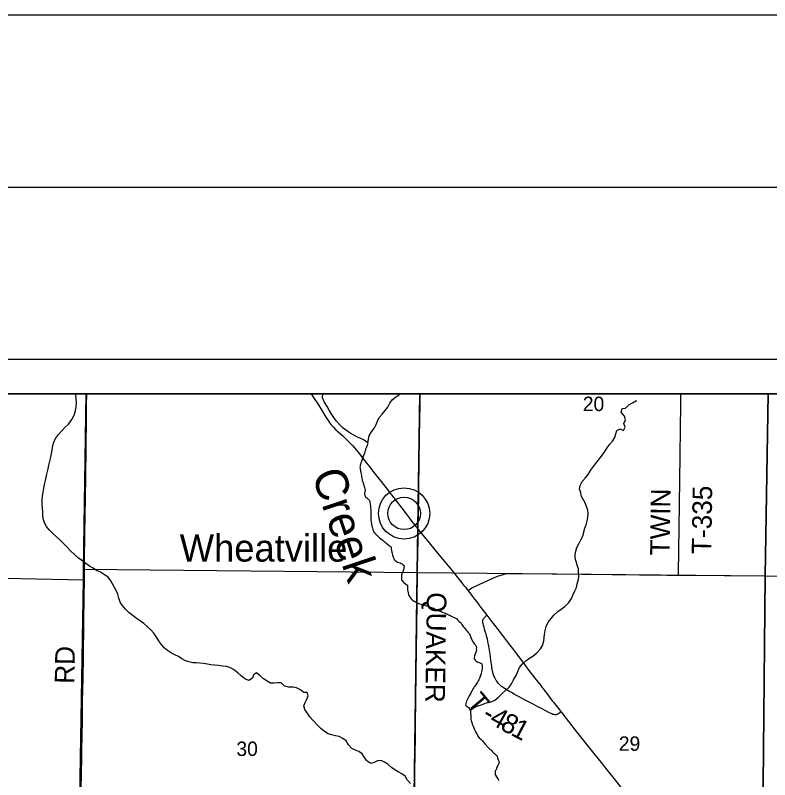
# Model space of a CAD drawing. Extents: x 0 to 34, y 0 to 22.
# Drawn here: x 3.317 to 5.509, y 19.778 to 22 of the extents above; entities that cross this region are included whole.
import ezdxf

# ---------------------------------------------------------------- set-up
doc = ezdxf.new("R2010")
doc.units = 0
for name, color, linetype in [('GM_X_Corporation', 7, 'Continuous'), ('GM_X_County_Road', 7, 'Continuous'), ('GM_X_County_Road_Text', 7, 'Continuous'), ('GM_X_Minor_River', 7, 'Continuous'), ('GM_X_Minor_River_Text', 7, 'Continuous'), ('GM_X_Section_Text', 7, 'Continuous'), ('GM_X_State_Route', 7, 'Continuous'), ('GM_X_Township_Road', 7, 'Continuous'), ('GM_X_Township_Road_Text', 7, 'Continuous'), ('GM_X_Unincorporated', 7, 'Continuous'), ('GM_X_Unincorporated_Location', 7, 'Continuous'), ('GM_X_Unincorporated_Text', 7, 'Continuous'), ('SH_Border', 7, 'Continuous'), ('SH_Cut_Line', 7, 'Continuous'), ('SH_Data', 7, 'Continuous')]:
    doc.layers.add(name, color=color, linetype=linetype)

msp = doc.modelspace()

# ---------------------------------------------------------------- linework, layer by layer
at = {"layer": 'GM_X_Corporation'}
for points in [[(3.5082, 19.7748), (3.5095, 19.8637), (3.511, 19.9493), (3.5112, 20.0053), (3.5125, 20.0737), (3.5137, 20.1344), (3.5145, 20.2333), (3.5155, 20.3135), (3.5163, 20.3526), (3.5169, 20.4148), (3.5181, 20.4924), (3.5191, 20.549), (3.5197, 20.5949), (3.5203, 20.6635), (3.5214, 20.7384), (3.5224, 20.8347), (3.5228, 20.8664), (3.5231, 20.9), (2.1, 20.9)], [(8.9, 20.9), (3.5231, 20.9), (3.5228, 20.8664), (3.5224, 20.8347), (3.5214, 20.7384), (3.5203, 20.6635), (3.5197, 20.5949), (3.5191, 20.549), (3.5181, 20.4924), (3.5169, 20.4148), (3.5163, 20.3526), (3.5155, 20.3135), (3.5145, 20.2333), (3.5137, 20.1344), (3.5125, 20.0737), (3.5112, 20.0053), (3.511, 19.9493), (3.5095, 19.8637), (3.5082, 19.7748)]]:
    msp.add_lwpolyline(points, dxfattribs=at)
for points in [[(3.5223, 20.9), (2.5175, 20.9), (2.5086, 20.3801), (3.5147, 20.359), (3.5146, 20.3904)], [(4.4918, 20.9), (3.5223, 20.9), (3.5146, 20.3904), (4.4842, 20.3804)], [(5.5043, 20.9), (4.4918, 20.9), (4.4842, 20.3804), (5.4958, 20.3705)], [(6.4979, 20.9), (5.5043, 20.9), (5.4958, 20.3705), (6.4927, 20.3511)], [(2.5086, 20.3801), (3.5147, 20.359), (3.4987, 19.3808), (2.4933, 19.3936)], [(3.5146, 20.3904), (4.4842, 20.3804), (4.4706, 19.3704), (3.4987, 19.3808), (3.5147, 20.359)], [(4.4842, 20.3804), (5.4958, 20.3705), (5.4859, 19.36), (4.4706, 19.3704)], [(5.4958, 20.3705), (6.4927, 20.3511), (6.4855, 19.3379), (5.4859, 19.36)]]:
    msp.add_lwpolyline(points, close=True, dxfattribs=at)
at = {"layer": 'GM_X_County_Road'}
msp.add_lwpolyline([(4.4772, 19.7476), (4.4779, 19.8035), (4.4785, 19.8518), (4.4793, 19.9021), (4.4797, 19.9332), (4.4798, 19.9611), (4.4802, 19.986), (4.4807, 20.0239), (4.4815, 20.076), (4.4818, 20.1021), (4.4823, 20.1394), (4.4826, 20.1698), (4.4832, 20.2058), (4.4836, 20.2444), (4.4839, 20.2711), (4.4845, 20.3077), (4.4846, 20.3257), (4.485, 20.3492), (4.4853, 20.3722), (4.4858, 20.4057), (4.4863, 20.4374), (4.4869, 20.4716), (4.4874, 20.5057), (4.4888, 20.6048), (4.4905, 20.7229), (4.4914, 20.7775), (4.492, 20.8205), (4.4929, 20.8733), (4.4933, 20.9)], dxfattribs=at)
at = {"layer": 'GM_X_Minor_River'}
for points in [[(3.8209, 20.1204), (3.8111, 20.1236), (3.8002, 20.1295), (3.7904, 20.1358), (3.7803, 20.1413), (3.7702, 20.1464), (3.7589, 20.1538), (3.7488, 20.1612), (3.7407, 20.172), (3.734, 20.182), (3.727, 20.1928), (3.7192, 20.2043), (3.7103, 20.214), (3.7006, 20.2225), (3.6902, 20.2322), (3.6804, 20.2392), (3.6688, 20.247), (3.6587, 20.2544), (3.6479, 20.2634), (3.637, 20.2734), (3.6274, 20.285), (3.6211, 20.2946), (3.6175, 20.3057), (3.6143, 20.3175), (3.6096, 20.3279), (3.5993, 20.347), (3.5938, 20.3566), (3.5868, 20.367), (3.5755, 20.3737), (3.5639, 20.3811), (3.553, 20.3863), (3.5429, 20.3925), (3.532, 20.3988), (3.5215, 20.4062), (3.5103, 20.4152), (3.5005, 20.4225), (3.4904, 20.4303), (3.4755, 20.445), (3.4666, 20.4547), (3.4569, 20.4648), (3.4469, 20.4748), (3.4353, 20.4853), (3.4256, 20.4942), (3.4155, 20.5043), (3.407, 20.5139), (3.4011, 20.5243), (3.3983, 20.5338), (3.3962, 20.5445), (3.3964, 20.5563), (3.3955, 20.5673), (3.3949, 20.5798), (3.3951, 20.5905), (3.3957, 20.603), (3.3975, 20.614), (3.3996, 20.6257), (3.4017, 20.6359), (3.4045, 20.6477), (3.4075, 20.662), (3.4124, 20.6817), (3.4145, 20.6919), (3.4202, 20.7157), (3.4219, 20.726), (3.4236, 20.7358), (3.4258, 20.7491), (3.429, 20.7596), (3.4333, 20.7694), (3.4423, 20.7818), (3.4523, 20.7919), (3.4609, 20.8016), (3.4709, 20.812), (3.4807, 20.8255), (3.4877, 20.8379), (3.4917, 20.85), (3.4939, 20.8629), (3.4941, 20.8735), (3.4932, 20.8857), (3.4926, 20.8967), (3.4923, 20.9)], [(4.3406, 20.7571), (4.3306, 20.7649), (4.3204, 20.7696), (4.3107, 20.774), (4.3005, 20.7795), (4.29, 20.7858), (4.2795, 20.7928), (4.269, 20.8002), (4.2586, 20.811), (4.2504, 20.8207), (4.2423, 20.8311), (4.2349, 20.8422), (4.229, 20.8518), (4.2228, 20.863), (4.2143, 20.876), (4.2096, 20.8883), (4.2105, 20.8993), (4.2106, 20.9)], [(4.3406, 20.7571), (4.3445, 20.7775), (4.3512, 20.7888), (4.3605, 20.8008), (4.3656, 20.8109), (4.3692, 20.8207), (4.3739, 20.8305), (4.3825, 20.8402), (4.3914, 20.8511), (4.3988, 20.8612), (4.4047, 20.8721), (4.4121, 20.8818), (4.4221, 20.8911), (4.4317, 20.897), (4.4343, 20.9)], [(4.6381, 19.9806), (4.6486, 19.9867), (4.6582, 19.9915), (4.6681, 19.9951), (4.6781, 19.9983), (4.6884, 20.0023), (4.6994, 20.004), (4.7105, 20.0091), (4.7205, 20.0177), (4.731, 20.0285), (4.7418, 20.0382), (4.7514, 20.0475), (4.7588, 20.0572), (4.7647, 20.0685), (4.773, 20.0831), (4.7769, 20.0929), (4.7821, 20.1038), (4.7899, 20.1143), (4.7999, 20.124), (4.8107, 20.131), (4.8206, 20.1373), (4.8318, 20.1473), (4.8423, 20.1582), (4.8482, 20.1683), (4.8522, 20.1811), (4.8535, 20.191), (4.8541, 20.2005), (4.8565, 20.2118), (4.8594, 20.2235), (4.8646, 20.2356), (4.8735, 20.2468), (4.8817, 20.2565), (4.8932, 20.2669), (4.9028, 20.274), (4.9132, 20.2817), (4.9248, 20.2929), (4.9326, 20.3049), (4.9378, 20.3162), (4.9429, 20.3271), (4.9473, 20.3369), (4.9497, 20.3479), (4.953, 20.3596), (4.9539, 20.3698), (4.9534, 20.3808), (4.9528, 20.3911), (4.9496, 20.4018), (4.9467, 20.4121), (4.9439, 20.422), (4.9437, 20.4323), (4.945, 20.4421), (4.9487, 20.4534), (4.9542, 20.4636), (4.9604, 20.4749), (4.9667, 20.4877), (4.9688, 20.4986), (4.9717, 20.5088), (4.9757, 20.5194), (4.9785, 20.5303), (4.9802, 20.5406), (4.9816, 20.5516), (4.9799, 20.5611), (4.9766, 20.5721), (4.9723, 20.5829), (4.9613, 20.6028), (4.9603, 20.6131), (4.9556, 20.623), (4.9577, 20.6336), (4.9639, 20.6445), (4.9725, 20.6546), (4.981, 20.6655), (4.9884, 20.6771), (5.0056, 20.7003), (5.0145, 20.7112), (5.0219, 20.7216), (5.0297, 20.7321), (5.0363, 20.7423), (5.0433, 20.7524), (5.0522, 20.7621), (5.0589, 20.773), (5.0614, 20.7836), (5.0642, 20.7934), (5.0741, 20.7981), (5.0839, 20.793), (5.089, 20.8032), (5.085, 20.8131), (5.0902, 20.8244), (5.0866, 20.8351), (5.0769, 20.8463), (5.0798, 20.8572), (5.0897, 20.8578), (5.0993, 20.8675), (5.1097, 20.8734), (5.1193, 20.8793), (5.1223, 20.8796)], [(4.3406, 20.7571), (4.3388, 20.7492), (4.3372, 20.745), (4.3359, 20.7428), (4.3347, 20.7386), (4.3338, 20.736), (4.3325, 20.7318), (4.3309, 20.7277), (4.3271, 20.7176), (4.3262, 20.7149), (4.3254, 20.7115), (4.3241, 20.7085), (4.3233, 20.7059), (4.3224, 20.7029), (4.3211, 20.6987), (4.3202, 20.6946), (4.319, 20.6916), (4.3185, 20.6889), (4.3181, 20.6866), (4.3183, 20.6836), (4.319, 20.6809), (4.3193, 20.6782), (4.3199, 20.6744), (4.3209, 20.6705), (4.3215, 20.6663), (4.3225, 20.6621), (4.3228, 20.6586), (4.3234, 20.6544), (4.3244, 20.651), (4.325, 20.6475), (4.3264, 20.644), (4.3271, 20.6413), (4.3284, 20.6371), (4.3311, 20.6271), (4.3325, 20.6236), (4.3332, 20.6217), (4.3331, 20.6198), (4.3317, 20.6107), (4.3316, 20.608), (4.3319, 20.6049), (4.3336, 20.6014), (4.3355, 20.5995), (4.338, 20.5975), (4.3402, 20.5955), (4.3432, 20.5927), (4.3457, 20.59), (4.3464, 20.588), (4.347, 20.5834), (4.348, 20.5781), (4.3486, 20.5731), (4.3487, 20.5677), (4.3494, 20.5639), (4.3496, 20.5597), (4.3497, 20.5528), (4.3499, 20.5464), (4.3501, 20.541), (4.35, 20.5376), (4.3502, 20.5338), (4.3501, 20.5311), (4.3504, 20.528), (4.3511, 20.5257), (4.3513, 20.5227), (4.3519, 20.5181), (4.3526, 20.5161), (4.3537, 20.5142), (4.3536, 20.5123), (4.3543, 20.5104), (4.3552, 20.5046), (4.3563, 20.5027), (4.3574, 20.5003), (4.3588, 20.498), (4.361, 20.4956), (4.3628, 20.4933), (4.3654, 20.4909), (4.368, 20.4893), (4.3687, 20.4874), (4.3712, 20.485), (4.3749, 20.4814), (4.3789, 20.4778), (4.3823, 20.4754), (4.3852, 20.4734), (4.3885, 20.4706), (4.3911, 20.4686), (4.3941, 20.4659), (4.3985, 20.4626), (4.4029, 20.459), (4.4062, 20.4563), (4.4085, 20.4554), (4.4087, 20.4505), (4.4099, 20.4435), (4.4116, 20.437), (4.4129, 20.4309), (4.415, 20.4251), (4.4167, 20.4208), (4.4178, 20.4181), (4.4196, 20.4158), (4.4244, 20.4125), (4.4274, 20.4105), (4.4311, 20.4092), (4.4345, 20.408), (4.4382, 20.4067)], [(4.4382, 20.4067), (4.4408, 20.4055), (4.4434, 20.4031), (4.4464, 20.4011), (4.4466, 20.3984), (4.4461, 20.395), (4.446, 20.3923), (4.4452, 20.3897), (4.4451, 20.3878), (4.4439, 20.3855), (4.4423, 20.3829), (4.4407, 20.3795), (4.4402, 20.3761), (4.4393, 20.372), (4.4392, 20.3693), (4.4391, 20.3674), (4.4386, 20.3644), (4.4389, 20.3621), (4.4392, 20.3594), (4.4406, 20.3567), (4.4424, 20.3539), (4.445, 20.3519), (4.4509, 20.3479), (4.4546, 20.3444), (4.456, 20.3424), (4.456, 20.3405), (4.4562, 20.3367), (4.4565, 20.334), (4.4567, 20.3298), (4.4573, 20.3252), (4.458, 20.3229), (4.4583, 20.3206), (4.459, 20.3187), (4.4596, 20.3148), (4.461, 20.3121), (4.4639, 20.3074), (4.4672, 20.3043), (4.4698, 20.3023), (4.4712, 20.3003), (4.4738, 20.2983), (4.4768, 20.2967), (4.4794, 20.2947), (4.4827, 20.2934), (4.4868, 20.2914), (4.4913, 20.2897), (4.4962, 20.2883), (4.4996, 20.2875), (4.5022, 20.287), (4.5064, 20.2857), (4.509, 20.2845), (4.5116, 20.2836), (4.5183, 20.2811), (4.5232, 20.2801), (4.5258, 20.2789), (4.5284, 20.278), (4.5326, 20.2764), (4.5348, 20.2744), (4.5378, 20.2731), (4.5415, 20.2715), (4.5448, 20.2702), (4.5482, 20.2693), (4.5509, 20.2685), (4.5553, 20.2664), (4.5583, 20.2648), (4.5624, 20.2635), (4.5662, 20.2618), (4.5695, 20.2602), (4.5729, 20.2589), (4.5759, 20.2576), (4.5792, 20.256), (4.5822, 20.2544), (4.5855, 20.2527), (4.5896, 20.2507), (4.5934, 20.249), (4.599, 20.2469), (4.6026, 20.2418), (4.6063, 20.2379), (4.6099, 20.2347), (4.6125, 20.2331), (4.6139, 20.2296), (4.6161, 20.2261), (4.6182, 20.2233), (4.6219, 20.2194), (4.6237, 20.2163), (4.6266, 20.2131), (4.6295, 20.2096), (4.6328, 20.206), (4.6353, 20.2029), (4.6368, 20.2002), (4.6382, 20.1971), (4.6403, 20.1917), (4.6434, 20.1847), (4.6473, 20.1777), (4.6513, 20.1722), (4.6546, 20.1683), (4.656, 20.1663), (4.6563, 20.1617), (4.6561, 20.1572), (4.6564, 20.1553), (4.6559, 20.1507), (4.6542, 20.1462)], [(4.6542, 20.1462), (4.6526, 20.1428), (4.651, 20.1402), (4.6505, 20.1376), (4.65, 20.1338), (4.6503, 20.1315), (4.6509, 20.1288), (4.6527, 20.126), (4.6557, 20.1229), (4.6582, 20.1213), (4.6609, 20.12), (4.6642, 20.1184), (4.6695, 20.1167), (4.6721, 20.1151), (4.6737, 20.1093), (4.6736, 20.104), (4.6731, 20.1005), (4.6721, 20.0952), (4.6707, 20.088), (4.669, 20.0828), (4.6678, 20.0798), (4.6673, 20.0764), (4.6657, 20.0738), (4.6648, 20.0707), (4.6632, 20.0681), (4.6612, 20.0651), (4.6596, 20.0618), (4.6576, 20.0584), (4.6551, 20.0539), (4.6523, 20.0502), (4.6504, 20.0476), (4.6483, 20.0439), (4.6463, 20.0413), (4.6447, 20.0391), (4.6431, 20.0357), (4.6407, 20.032), (4.639, 20.0278), (4.637, 20.0249), (4.635, 20.0215), (4.6317, 20.014), (4.6297, 20.0099), (4.628, 20.0061), (4.6268, 20.0028), (4.6259, 19.999), (4.625, 19.9944), (4.6272, 19.9924), (4.6294, 19.9908), (4.6316, 19.9889), (4.6338, 19.9876), (4.6381, 19.9806), (4.6392, 19.9783), (4.6391, 19.9764), (4.6394, 19.9737), (4.6393, 19.9718), (4.6397, 19.9699), (4.6399, 19.9672), (4.6402, 19.9645), (4.6401, 19.9619), (4.6404, 19.9592), (4.6402, 19.9543), (4.6416, 19.9493), (4.6427, 19.9473), (4.6433, 19.9446), (4.6443, 19.94), (4.6467, 19.9334), (4.6509, 19.9245), (4.652, 19.9218), (4.6531, 19.9199), (4.6537, 19.9176), (4.6555, 19.9141), (4.6573, 19.911), (4.6591, 19.9082), (4.6616, 19.9039), (4.6649, 19.9), (4.6689, 19.8961), (4.6718, 19.8933), (4.6744, 19.8909), (4.6766, 19.8885), (4.6777, 19.8866), (4.6806, 19.8827), (4.6915, 19.8709), (4.6952, 19.8673), (4.6981, 19.8649), (4.6999, 19.8626), (4.7029, 19.8594), (4.7058, 19.8566), (4.7091, 19.8538), (4.7113, 19.8519), (4.7135, 19.8495), (4.7157, 19.8483), (4.7164, 19.846), (4.7174, 19.8413), (4.7199, 19.8363), (4.7212, 19.8324), (4.7223, 19.8297), (4.7218, 19.8256), (4.7189, 19.8196), (4.7165, 19.8166), (4.716, 19.8136), (4.7139, 19.8072), (4.7115, 19.8035)], [(4.4651, 19.7673), (4.4554, 19.7781), (4.4492, 19.7881), (4.4394, 19.7947), (4.4293, 19.8006), (4.4195, 19.8065), (4.4098, 19.8139), (4.3994, 19.8228), (4.3896, 19.829), (4.3798, 19.8338), (4.3692, 19.8332), (4.3596, 19.8277), (4.3493, 19.8249), (4.3384, 19.8326), (4.3314, 19.843), (4.3248, 19.8534), (4.3147, 19.8604), (4.3049, 19.8636), (4.2947, 19.8691), (4.2847, 19.8799), (4.2781, 19.8907), (4.2683, 19.8981), (4.2574, 19.904), (4.2472, 19.9053), (4.2351, 19.9082), (4.2253, 19.911), (4.2152, 19.918), (4.2047, 19.927), (4.1947, 19.9363), (4.1824, 19.9498), (4.1727, 19.9613), (4.1646, 19.9721), (4.1583, 19.9817), (4.1551, 19.9924), (4.1587, 20.0026), (4.1638, 20.0124), (4.1678, 20.0222), (4.1649, 20.0317), (4.1554, 20.0319), (4.1449, 20.0389), (4.1341, 20.0456), (4.1238, 20.0469), (4.1102, 20.0475), (4.0985, 20.05), (4.0888, 20.0593), (4.0789, 20.0599), (4.0683, 20.0589), (4.058, 20.0587), (4.0483, 20.0642), (4.0378, 20.0716), (4.0281, 20.0798), (4.018, 20.0883), (4.0084, 20.0832), (4.0056, 20.0734), (3.9952, 20.0667), (3.9835, 20.0711), (3.9731, 20.0797), (3.963, 20.089), (3.951, 20.0987), (3.9397, 20.1042), (3.9299, 20.107), (3.9197, 20.1084), (3.9072, 20.1097), (3.8959, 20.1111), (3.8849, 20.1124), (3.875, 20.1137), (3.8633, 20.1159), (3.8531, 20.1168), (3.8425, 20.1174), (3.8326, 20.1183), (3.8209, 20.1204)], [(4.7115, 19.8035), (4.711, 19.8012), (4.7109, 19.797), (4.7115, 19.7935), (4.7122, 19.7909), (4.7151, 19.7862), (4.7169, 19.7838), (4.7191, 19.7811), (4.7197, 19.7792), (4.7208, 19.7761)]]:
    msp.add_lwpolyline(points, dxfattribs=at)
at = {"layer": 'GM_X_State_Route'}
for points in [[(4.1764, 20.9), (4.1768, 20.8994), (4.1855, 20.8866), (4.1958, 20.8703), (4.2063, 20.8528), (4.2189, 20.832), (4.2236, 20.8247), (4.2287, 20.8175), (4.2349, 20.8097), (4.241, 20.8026), (4.2479, 20.7954), (4.2547, 20.789), (4.2691, 20.7762), (4.2819, 20.7644), (4.2898, 20.7566), (4.2974, 20.7485), (4.3035, 20.7415), (4.3155, 20.7265), (4.3354, 20.701), (4.3477, 20.6853), (4.3587, 20.6713)], [(4.3587, 20.6713), (4.3797, 20.6449), (4.4237, 20.5886), (4.4369, 20.5714), (4.4528, 20.5507), (4.4616, 20.5388), (4.4638, 20.5358), (4.4691, 20.5289), (4.4852, 20.5084), (4.4874, 20.5057), (4.5192, 20.4663), (4.5487, 20.4303), (4.5646, 20.4111), (4.5887, 20.3827), (4.5989, 20.3702), (4.6105, 20.3556), (4.6204, 20.3429), (4.6245, 20.3374), (4.6323, 20.3274), (4.6363, 20.3222), (4.6401, 20.3173), (4.645, 20.3109), (4.6511, 20.303), (4.6564, 20.2961), (4.6602, 20.2912), (4.6636, 20.2868), (4.6696, 20.2789), (4.6869, 20.2561), (4.6988, 20.2407), (4.7131, 20.222), (4.7354, 20.193), (4.75, 20.174), (4.761, 20.1597), (4.7727, 20.1444), (4.7882, 20.1235), (4.8092, 20.0957), (4.8264, 20.0736), (4.8434, 20.0515), (4.8469, 20.0471), (4.8491, 20.0442), (4.8563, 20.0348), (4.8609, 20.0289), (4.8771, 20.0077), (4.8813, 20.0023), (4.8836, 19.9994), (4.8874, 19.9945), (4.8928, 19.9876), (4.9012, 19.9769), (4.9026, 19.9751), (4.9105, 19.9651), (4.9474, 19.9175), (4.9668, 19.8932), (4.9738, 19.8845), (5.0017, 19.8495), (5.0106, 19.8384), (5.0231, 19.8229), (5.032, 19.8118), (5.0567, 19.7806), (5.0776, 19.7544)]]:
    msp.add_lwpolyline(points, dxfattribs=at)
at = {"layer": 'GM_X_Township_Road'}
for points in [[(3.5031, 19.3798), (3.5032, 19.3854), (3.5038, 19.4345), (3.5048, 19.5165), (3.5064, 19.6133), (3.5074, 19.6792), (3.5085, 19.7743), (3.5098, 19.8632), (3.5112, 19.9487), (3.5114, 20.0048), (3.5127, 20.0731), (3.5139, 20.1338), (3.5147, 20.2328), (3.5157, 20.313), (3.5165, 20.3521), (3.5172, 20.4142), (3.5183, 20.4919), (3.5194, 20.5485), (3.5199, 20.5944), (3.5206, 20.6629), (3.5216, 20.7379), (3.5226, 20.8342), (3.523, 20.8659), (3.5234, 20.9)], [(5.2433, 20.3727), (5.2434, 20.3786), (5.2448, 20.4433), (5.2475, 20.6477), (5.2503, 20.8703), (5.2509, 20.9)], [(4.6323, 20.3274), (4.6362, 20.3307), (4.6398, 20.3332), (4.6434, 20.3354), (4.7112, 20.3666), (4.7204, 20.3704), (4.728, 20.373), (4.7346, 20.3748), (4.7407, 20.3761), (4.7487, 20.3771), (4.7567, 20.3777), (4.7698, 20.3779), (4.7897, 20.3776), (5.0499, 20.3748), (5.2096, 20.3729), (5.2433, 20.3727), (5.3773, 20.3715), (5.6065, 20.3695)], [(4.9026, 19.9751), (4.8994, 19.9729), (4.896, 19.9705), (4.8927, 19.9687), (4.8914, 19.9681), (4.8898, 19.9676), (4.8876, 19.9671), (4.8858, 19.967), (4.8841, 19.9671), (4.8818, 19.9673), (4.8804, 19.9677), (4.8788, 19.9681), (4.8754, 19.9695), (4.8689, 19.9728), (4.8562, 19.9794), (4.8461, 19.9846), (4.8352, 19.9903), (4.821, 19.9976), (4.8074, 20.0046), (4.7944, 20.0115), (4.7805, 20.0188), (4.7732, 20.0228), (4.7665, 20.0263), (4.758, 20.0313), (4.7524, 20.0345), (4.7479, 20.0372), (4.7383, 20.0429), (4.7341, 20.0457), (4.7316, 20.0476), (4.7291, 20.0495), (4.7252, 20.0532), (4.7235, 20.0548), (4.7217, 20.0567), (4.7198, 20.0587), (4.7174, 20.0617), (4.7157, 20.0641), (4.7143, 20.0663), (4.713, 20.0686), (4.7119, 20.0707), (4.7103, 20.0738), (4.709, 20.0769), (4.7076, 20.0801), (4.7064, 20.0832), (4.7055, 20.086), (4.7045, 20.089), (4.7038, 20.0915), (4.7032, 20.0937), (4.7022, 20.0988), (4.7015, 20.1035), (4.7009, 20.1086), (4.6986, 20.126), (4.6974, 20.1352), (4.6963, 20.1432), (4.6949, 20.1545), (4.693, 20.1663), (4.6901, 20.1801), (4.6883, 20.1874), (4.6871, 20.1922), (4.6858, 20.1969), (4.6844, 20.202), (4.6833, 20.2056), (4.6822, 20.2093), (4.6804, 20.2152), (4.6787, 20.2211), (4.6772, 20.2266), (4.6759, 20.2318), (4.6752, 20.2341), (4.675, 20.2363), (4.6749, 20.2379), (4.6749, 20.2398), (4.6751, 20.2412), (4.6756, 20.2428), (4.6762, 20.2441), (4.6769, 20.2453), (4.6779, 20.2466), (4.6789, 20.2479), (4.6801, 20.2493), (4.6869, 20.2561)]]:
    msp.add_lwpolyline(points, dxfattribs=at)
at = {"layer": 'GM_X_Unincorporated'}
for radius in [0.0744, 0.0472]:
    msp.add_circle((4.4464, 20.5521), radius, dxfattribs=at)
at = {"layer": 'GM_X_Unincorporated_Location'}
msp.add_line((4.4464, 20.5521), (4.4464, 20.5521), dxfattribs=at)
at = {"layer": 'SH_Border'}
msp.add_lwpolyline([(1.5, 21.5), (33.5, 21.5), (33.5, 0.5), (1.5, 0.5)], close=True, dxfattribs=at)
at = {"layer": 'SH_Cut_Line'}
msp.add_lwpolyline([(0, 0), (34, 0), (34, 22), (0, 22)], close=True, dxfattribs=at)
at = {"layer": 'SH_Data'}
for p, q in [((2, 21), (9, 21)), ((2.1, 20.9), (8.9, 20.9)), ((2.1, 20.9), (8.9, 20.9)), ((2.1, 20.9), (8.9, 20.9))]:
    msp.add_line(p, q, dxfattribs=at)

# ---------------------------------------------------------------- texts
at = {"layer": 'GM_X_County_Road_Text'}
msp.add_text('QUAKER', height=0.05682, rotation=269.1746, dxfattribs=at).set_placement((4.5128, 20.3232))
at = {"layer": 'GM_X_Minor_River_Text'}
msp.add_text('Creek', height=0.09479, rotation=288.4598, dxfattribs=at).set_placement((4.1775, 20.666))
at = {"layer": 'GM_X_Section_Text'}
for s, p in [('20', (4.9657, 20.8496)), ('30', (3.9591, 19.8471)), ('29', (5.0703, 19.8621))]:
    msp.add_text(s, height=0.04186, rotation=0, dxfattribs=at).set_placement(p)
at = {"layer": 'GM_X_Township_Road_Text'}
for s, height, rotation, p in [('T-335', 0.05682, 89.1574, (5.3389, 20.4339)), ('TWIN', 0.05682, 89.2079, (5.218, 20.4298)), ('RD', 0.05682, 89.0118, (3.488, 20.0566)), ('T', 0.0568, 309.9082, (4.6258, 20.0017)), ('-', 0.0568, 330.3626, (4.6699, 19.955)), ('4', 0.0568, 331.2887, (4.6911, 19.943)), ('8', 0.0568, 332.1189, (4.7225, 19.9257)), ('1', 0.0568, 332.3112, (4.7537, 19.9093))]:
    msp.add_text(s, height=height, rotation=rotation, dxfattribs=at).set_placement(p)
at = {"layer": 'GM_X_Unincorporated_Text'}
msp.add_text('Wheatville', height=0.07898, rotation=0, dxfattribs=at).set_placement((3.7945, 20.412))

doc.saveas('drawing.dxf')
